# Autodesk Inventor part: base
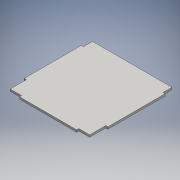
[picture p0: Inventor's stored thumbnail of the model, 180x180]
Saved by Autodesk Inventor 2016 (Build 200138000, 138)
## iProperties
Created: 2016-06
Part Number: base
Material: Genérico
Document SubType Name: Modeling
Designer: adm
Density: 1 g/cm^3
Appearance: Valor por defecto
Author: adm
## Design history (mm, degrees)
sketch "Boceto1"
  geometry: L1 (58, -33.541)-(58, 46.459); L2 (55, 59)-(-56, 59); L3 (-59, 46.459)-(-59, -33.541); L4 (-58, -56)-(58, 56); L5 (58, -56)-(-58, 56); L6 (-56, 59)-(-56, 46.459); L7 (-56, -33.541)-(-56, -56); L8 (-59, 46.459)-(-56, 46.459); L9 (55, 46.459)-(58, 46.459); L10 (55, -56)-(55, -33.541); L11 (55, 46.459)-(55, 59); L12 (-59, -33.541)-(-56, -33.541); L13 (55, -33.541)-(58, -33.541); L14 (-56, -54)-(-55.929, -54); L15 (55.929, -54)-(55, -54); L16 (-40, -56)-(-40, -59); L17 (40, -56)-(40, -59); L18 (-40, -59)-(40, -59); L19 (-56, -56)-(-40, -56); L20 (40, -56)-(55, -56); 2 further points
  constraints: 40 end point, 7 parallel, 7 perpendicular, 4 point on line, 2 horizontal, 2 midpoint
  dimensions: "d1" = 112 distance of L4.end L5.start; "d10" = 80 distance of L1.start L1.end; "d16" = 3 distance between parallel lines of L11 L1; "d17" = 3 distance between parallel lines of L10 L1; "d18" = 3 distance between parallel lines of L7 L3; "d22" = 59 distance from line of point (0, 0) L18; "d23" = 22.459 distance between parallel lines of L12 L19
extrude "Extrusión1" new body sketch "Boceto1" distance "d14" = 3; taper "d15" = 0 deg
node "Sólido1"
other parameters: "d2" = 2, "d3" = 3, "d4" = 3, "d7" = 15, "d8" = 15, "d13" = 3
